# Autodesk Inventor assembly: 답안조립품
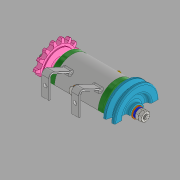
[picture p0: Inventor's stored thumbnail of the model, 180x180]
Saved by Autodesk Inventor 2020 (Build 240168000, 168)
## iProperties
Created: 2021-12
Part Number: 답안조립품
Document SubType Name: Assembly
Designer: MIRAE
Author: MIRAE
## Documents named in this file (16)
- C:\Users\MIRAE\Desktop\711206V1029\답안조립품.iam
- C:\Users\MIRAE\Desktop\711206V1029\본체.ipt
- C:\Users\MIRAE\Desktop\711206V1029\V벨트풀리.ipt
- C:\Users\MIRAE\Desktop\711206V1029\너트 M8.ipt
- C:\Users\MIRAE\Desktop\711206V1029\니플 M6 x 0.75.ipt
- C:\Users\MIRAE\Desktop\711206V1029\베어링 6002.ipt
- C:\Users\MIRAE\Desktop\711206V1029\볼트 M4 x 12.ipt
- C:\Users\MIRAE\Desktop\711206V1029\볼트 M6 x 8.ipt
- C:\Users\MIRAE\Desktop\711206V1029\스프로킷.ipt
- C:\Users\MIRAE\Desktop\711206V1029\스프링와셔 8.ipt
- C:\Users\MIRAE\Desktop\711206V1029\오일 실 15 x 25 x 7.ipt
- C:\Users\MIRAE\Desktop\711206V1029\와셔 6 x 11.5.ipt
- C:\Users\MIRAE\Desktop\711206V1029\와셔 8 x 17.ipt
- C:\Users\MIRAE\Desktop\711206V1029\축.ipt
- C:\Users\MIRAE\Desktop\711206V1029\커버.ipt
- C:\Users\MIRAE\Desktop\711206V1029\키 3 x 3.ipt
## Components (11 placed, 3 different names)
1. V벨트풀리:1
2. KS B 2023 6002 - 15 x 32 x 9:1
3. KS B 2023 6002 - 15 x 32 x 9:2
4. ISO 4762 M4 x 12:1 — 각도:2
5. ISO 4762 M4 x 12:3
6. ISO 4762 M4 x 12:4
7. ISO 4762 M4 x 12:5
8. ISO 4762 M4 x 12:2 — 각도:1
9. ISO 4762 M4 x 12:6
10. ISO 4762 M4 x 12:7
11. ISO 4762 M4 x 12:8
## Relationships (2: Angle 2)
- 각도:1 [Angle]: ISO 4762 M4 x 12:2
- 각도:2 [Angle]: ISO 4762 M4 x 12:1
